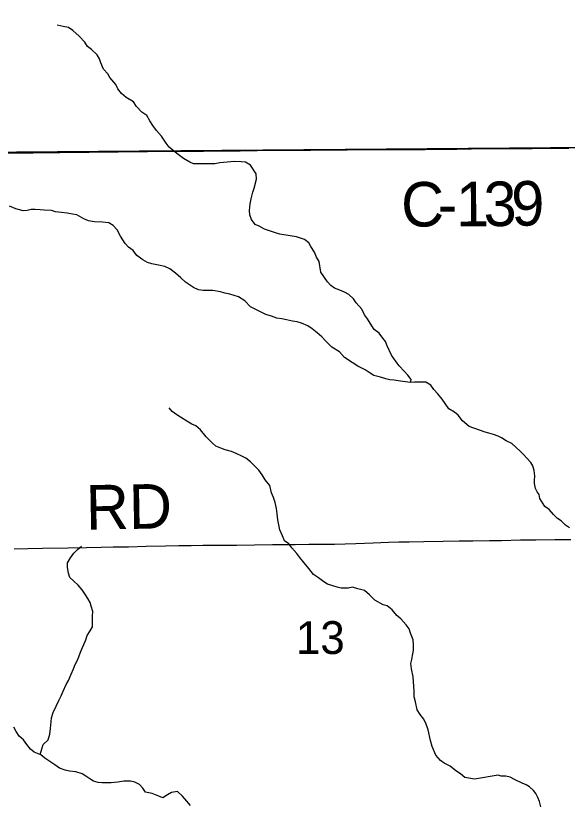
# Model space of a CAD drawing. Extents: x 0 to 34, y 0 to 22.
# Drawn here: x 4.762 to 5.466, y 19.089 to 20.093 of the extents above; entities that cross this region are included whole.
import ezdxf

# ---------------------------------------------------------------- set-up
doc = ezdxf.new("R2010")
doc.units = 0
for name, color, linetype in [('Default', 7, 'Continuous'), ('GM_X_County_Road', 7, 'Continuous'), ('GM_X_County_Road_Text', 7, 'Continuous'), ('GM_X_Minor_River', 7, 'Continuous'), ('GM_X_Section', 7, 'Continuous'), ('GM_X_Section_Text', 7, 'Continuous'), ('GM_X_Township_Road', 7, 'Continuous'), ('GM_X_Township_Road_Text', 7, 'Continuous')]:
    doc.layers.add(name, color=color, linetype=linetype)

msp = doc.modelspace()

# ---------------------------------------------------------------- linework, layer by layer
at = {"layer": 'Default'}
msp.add_lwpolyline([(5.6501, 20.9), (4.655, 20.9), (4.6576, 19.9182), (5.654, 19.9264)], close=True, dxfattribs=at)
at = {"layer": 'GM_X_County_Road'}
msp.add_lwpolyline([(4.7503, 19.9176), (4.8186, 19.9185), (4.9303, 19.9199), (4.9769, 19.9204), (5.0017, 19.9205), (5.0484, 19.9208), (5.0701, 19.9212), (5.1012, 19.9215), (5.1385, 19.9218), (5.1851, 19.9221), (5.2131, 19.9223), (5.2472, 19.9224), (5.2844, 19.9225), (5.3031, 19.9227), (5.3248, 19.923), (5.3435, 19.9233), (5.3776, 19.9236), (5.4211, 19.9239), (5.4677, 19.924)], dxfattribs=at)
at = {"layer": 'GM_X_Minor_River'}
for points in [[(5.2657, 19.6254), (5.2669, 19.6292), (5.2623, 19.6349), (5.2577, 19.6398), (5.2516, 19.6466), (5.2474, 19.6519), (5.2417, 19.6603), (5.2359, 19.672), (5.234, 19.6777), (5.2294, 19.6834), (5.226, 19.6883), (5.2195, 19.6929), (5.2145, 19.7012), (5.2111, 19.7065), (5.2073, 19.7118), (5.2038, 19.7187), (5.1965, 19.727), (5.1931, 19.7319), (5.187, 19.7376), (5.1817, 19.7406), (5.1756, 19.7432), (5.1691, 19.7455), (5.1642, 19.7489), (5.16, 19.7538), (5.1516, 19.7659), (5.1492, 19.7796), (5.1461, 19.7853), (5.1435, 19.7914), (5.1389, 19.7986), (5.1362, 19.8035), (5.1308, 19.8077), (5.1206, 19.8111), (5.1122, 19.8122), (5.0993, 19.8144), (5.0936, 19.8163), (5.0795, 19.8208), (5.0727, 19.8249), (5.0678, 19.8268), (5.0632, 19.8332), (5.0609, 19.8393), (5.0604, 19.8446), (5.0615, 19.8534), (5.0626, 19.8595), (5.0649, 19.8682), (5.0664, 19.8732), (5.0693, 19.8846), (5.0689, 19.8914), (5.0617, 19.9024), (5.0552, 19.9062), (5.0499, 19.9069), (5.0415, 19.9073), (5.0366, 19.9069), (5.0226, 19.9053), (5.0161, 19.9041), (5.0002, 19.904), (4.9949, 19.9044), (4.9892, 19.9044), (4.9842, 19.9062), (4.9762, 19.9108), (4.9678, 19.9172), (4.9579, 19.9255), (4.9541, 19.9304), (4.9484, 19.9395), (4.9419, 19.9467), (4.9373, 19.9532), (4.9335, 19.9592), (4.9296, 19.9657), (4.9232, 19.9702), (4.9163, 19.9774), (4.9125, 19.9831), (4.9033, 19.9888), (4.8972, 19.9937), (4.8927, 19.9997), (4.89, 20.0054), (4.8823, 20.0141), (4.8796, 20.0191), (4.8743, 20.0251), (4.8708, 20.0331), (4.8689, 20.038), (4.8662, 20.043), (4.859, 20.0502), (4.854, 20.0539), (4.8506, 20.0592), (4.8433, 20.0672), (4.8353, 20.0744), (4.8296, 20.0782), (4.8228, 20.0793), (4.8152, 20.0811)], [(5.3612, 19.562), (5.3408, 19.5691), (5.3321, 19.5763), (5.3267, 19.5835), (5.3218, 19.5873), (5.3149, 19.5918), (5.3103, 19.5986), (5.3061, 19.6043), (5.3008, 19.6107), (5.2958, 19.6164), (5.2916, 19.6221), (5.2855, 19.6259), (5.2711, 19.6258), (5.2654, 19.6254), (5.2502, 19.6276), (5.2449, 19.6284), (5.2396, 19.6287), (5.2342, 19.6302), (5.2278, 19.6321), (5.219, 19.6343), (5.213, 19.6381), (5.208, 19.6415), (5.1985, 19.646), (5.1913, 19.6509), (5.1817, 19.6573), (5.1752, 19.6645), (5.1657, 19.6702), (5.1577, 19.6781), (5.1528, 19.6834), (5.1467, 19.6887), (5.1406, 19.6937), (5.1348, 19.6974), (5.1269, 19.7008), (5.1212, 19.7027), (5.1155, 19.7034), (5.1075, 19.7053), (5.1018, 19.7064), (5.0953, 19.7075), (5.0885, 19.7098), (5.0813, 19.712), (5.0618, 19.7218), (5.0546, 19.7294), (5.0466, 19.7347), (5.0352, 19.738), (5.0291, 19.7392), (5.0234, 19.741), (5.0139, 19.7425), (5.0071, 19.7425), (5.0014, 19.7428), (4.9953, 19.7436), (4.9889, 19.7466), (4.9789, 19.7534), (4.9729, 19.7587), (4.966, 19.7647), (4.9587, 19.7704), (4.9523, 19.7734), (4.9443, 19.7749), (4.9359, 19.7767), (4.9302, 19.7782), (4.9242, 19.7816), (4.9169, 19.7873), (4.9119, 19.7937), (4.9062, 19.7979), (4.902, 19.8028), (4.8959, 19.8119), (4.8917, 19.8199), (4.8864, 19.8256), (4.881, 19.829), (4.873, 19.8297), (4.8628, 19.8304), (4.8552, 19.8315), (4.8491, 19.8341), (4.8404, 19.8391), (4.8347, 19.8402), (4.8278, 19.8413), (4.8206, 19.842), (4.813, 19.8431), (4.8077, 19.8446), (4.7986, 19.8453), (4.7933, 19.8457), (4.7872, 19.846), (4.7819, 19.846), (4.777, 19.8445), (4.7716, 19.8441), (4.7625, 19.8467), (4.7545, 19.8504)], [(5.3474, 19.1194), (5.3352, 19.1216), (5.3295, 19.1261), (5.3238, 19.1303), (5.3165, 19.1359), (5.3089, 19.1397), (5.304, 19.1431), (5.2982, 19.1499), (5.2936, 19.1613), (5.2913, 19.1689), (5.2882, 19.1826), (5.2859, 19.1898), (5.2828, 19.1962), (5.2782, 19.2019), (5.2744, 19.208), (5.2721, 19.2182), (5.2705, 19.2243), (5.2705, 19.2319), (5.2693, 19.2502), (5.2673, 19.2604), (5.2665, 19.2672), (5.2676, 19.2722), (5.2684, 19.2771), (5.2695, 19.2836), (5.2698, 19.2908), (5.2694, 19.2973), (5.2659, 19.3056), (5.264, 19.311), (5.2602, 19.3163), (5.2537, 19.3238), (5.2484, 19.328), (5.2426, 19.3356), (5.2361, 19.3405), (5.2312, 19.342), (5.2202, 19.3476), (5.2137, 19.3545), (5.2072, 19.3601), (5.1988, 19.3624), (5.192, 19.3642), (5.1863, 19.3631), (5.1776, 19.363), (5.1723, 19.3645), (5.1601, 19.3683), (5.1551, 19.3713), (5.1483, 19.3762), (5.1422, 19.3804), (5.1361, 19.3883), (5.1304, 19.3955), (5.1246, 19.4023), (5.1208, 19.4073), (5.1143, 19.4145), (5.1105, 19.4198), (5.1052, 19.4235), (5.1025, 19.4296), (5.099, 19.4376), (5.0978, 19.444), (5.0967, 19.4501), (5.0959, 19.4577), (5.0951, 19.4646), (5.0931, 19.4722), (5.0912, 19.4786), (5.0885, 19.4847), (5.0862, 19.4942), (5.0805, 19.5014), (5.0766, 19.5078), (5.0724, 19.5135), (5.0617, 19.5241), (5.0556, 19.529), (5.0507, 19.5313), (5.0435, 19.535), (5.0374, 19.5373), (5.0294, 19.5395), (5.0241, 19.5414), (5.0176, 19.5441), (5.0127, 19.5482), (5.005, 19.5562), (4.9978, 19.5649), (4.9921, 19.5702), (4.9867, 19.5724), (4.9806, 19.5762), (4.9726, 19.5811), (4.9677, 19.5841), (4.962, 19.5883), (4.9578, 19.5932)], [(5.4689, 19.44), (5.4635, 19.4433), (5.4581, 19.4489), (5.4535, 19.4519), (5.4485, 19.4572), (5.4427, 19.4632), (5.4373, 19.4673), (5.4307, 19.4775), (5.4299, 19.4824), (5.4276, 19.4861), (5.4252, 19.4903), (5.424, 19.4967), (5.424, 19.5005), (5.4243, 19.5062), (5.4238, 19.5131), (5.4218, 19.5191), (5.4195, 19.5233), (5.4141, 19.5289), (5.4095, 19.5341), (5.4056, 19.5379), (5.3952, 19.5476), (5.3879, 19.551), (5.3818, 19.5547), (5.3776, 19.5569), (5.3719, 19.5591), (5.3657, 19.5609), (5.3612, 19.562)], [(4.7934, 19.151), (4.7972, 19.1636), (4.8036, 19.1697), (4.8059, 19.1769), (4.8066, 19.1842), (4.8073, 19.1925), (4.8077, 19.1975), (4.8099, 19.2047), (4.814, 19.2127), (4.8174, 19.22), (4.82, 19.2257), (4.8227, 19.2318), (4.8264, 19.2401), (4.8294, 19.2455), (4.8328, 19.2535), (4.8358, 19.26), (4.8381, 19.2657), (4.8407, 19.2706), (4.8429, 19.2756), (4.8448, 19.2813), (4.8515, 19.2973), (4.8534, 19.3026), (4.8572, 19.3087), (4.8602, 19.3137), (4.8601, 19.3274), (4.8605, 19.3335), (4.8585, 19.3399), (4.857, 19.3448), (4.8543, 19.3498), (4.8512, 19.3547), (4.847, 19.3611), (4.8417, 19.3668), (4.8364, 19.3721), (4.8314, 19.3767), (4.8295, 19.3824), (4.8283, 19.3896), (4.8283, 19.3953), (4.832, 19.4018), (4.8362, 19.4075), (4.8411, 19.4124), (4.846, 19.4167)], [(4.8122, 19.1378), (4.8045, 19.1427), (4.7992, 19.1461), (4.7943, 19.1506), (4.7859, 19.154), (4.7809, 19.1578), (4.7763, 19.1635), (4.7721, 19.1696), (4.7668, 19.1745), (4.7626, 19.1802), (4.7599, 19.1858)], [(4.9851, 19.0861), (4.9805, 19.0914), (4.9748, 19.0979), (4.9687, 19.1039), (4.9611, 19.1024), (4.9558, 19.0993), (4.9501, 19.0958), (4.9448, 19.0977), (4.9364, 19.1011), (4.9277, 19.103), (4.9243, 19.1079), (4.9201, 19.1128), (4.9144, 19.1158), (4.9087, 19.1169), (4.9003, 19.1169), (4.8927, 19.1157), (4.884, 19.1149), (4.8726, 19.1149), (4.8673, 19.1152), (4.8616, 19.1171), (4.8567, 19.1201), (4.8517, 19.1235), (4.8468, 19.1262), (4.8391, 19.1288), (4.8308, 19.1299), (4.8251, 19.131), (4.8179, 19.1336), (4.8122, 19.1378)], [(5.3817, 19.1235), (5.3775, 19.1246), (5.3474, 19.1194)], [(5.432, 19.0843), (5.4304, 19.0911), (5.4285, 19.096), (5.4257, 19.1013), (5.4226, 19.1051), (5.4176, 19.1099), (5.4134, 19.1122), (5.4084, 19.1144), (5.3985, 19.1192), (5.3931, 19.1222), (5.3874, 19.1232), (5.3817, 19.1235)]]:
    msp.add_lwpolyline(points, dxfattribs=at)
at = {"layer": 'GM_X_Section'}
msp.add_lwpolyline([(4.6746, 18.9086), (5.6498, 18.8985), (5.6542, 19.8813), (5.654, 19.9264), (4.6576, 19.9182), (4.6526, 19.2311), (4.6746, 19.2311)], close=True, dxfattribs=at)
at = {"layer": 'GM_X_Township_Road'}
msp.add_lwpolyline([(4.7601, 19.4131), (4.7776, 19.4135), (4.7964, 19.4139), (4.8288, 19.4144), (4.8525, 19.4151), (4.8711, 19.4154), (4.8864, 19.4156), (4.9061, 19.4159), (4.9287, 19.4167), (4.9533, 19.4172), (4.9704, 19.4176), (4.986, 19.4176), (5.001, 19.4178), (5.0224, 19.4179), (5.0441, 19.4179), (5.09, 19.4188), (5.1189, 19.4188), (5.136, 19.419), (5.169, 19.4193), (5.196, 19.42), (5.2181, 19.4209), (5.2378, 19.4217), (5.2508, 19.4221), (5.264, 19.4222), (5.2829, 19.4224), (5.3074, 19.4228), (5.3281, 19.4234), (5.3454, 19.4233), (5.3666, 19.4238), (5.3821, 19.424), (5.4062, 19.4246), (5.4256, 19.4249), (5.45, 19.4252), (5.4704, 19.425)], dxfattribs=at)

# ---------------------------------------------------------------- texts
at = {"layer": 'GM_X_County_Road_Text'}
for s, rotation, p in [('C', 0.2849, (5.254, 19.8241)), ('1', 0.3508, (5.324, 19.8244)), ('3', 0.5394, (5.3592, 19.8246)), ('9', 1.2217, (5.395, 19.825)), ('-', 0.2987, (5.3006, 19.8243))]:
    msp.add_text(s, height=0.0568, rotation=rotation, dxfattribs=at).set_placement(p)
at = {"layer": 'GM_X_Section_Text'}
msp.add_text('13', height=0.04186, rotation=0, dxfattribs=at).set_placement((5.1197, 19.2791))
at = {"layer": 'GM_X_Township_Road_Text'}
msp.add_text('RD', height=0.05682, rotation=0.9788, dxfattribs=at).set_placement((4.8522, 19.4376))

doc.saveas('drawing.dxf')
